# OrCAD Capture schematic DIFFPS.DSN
size A
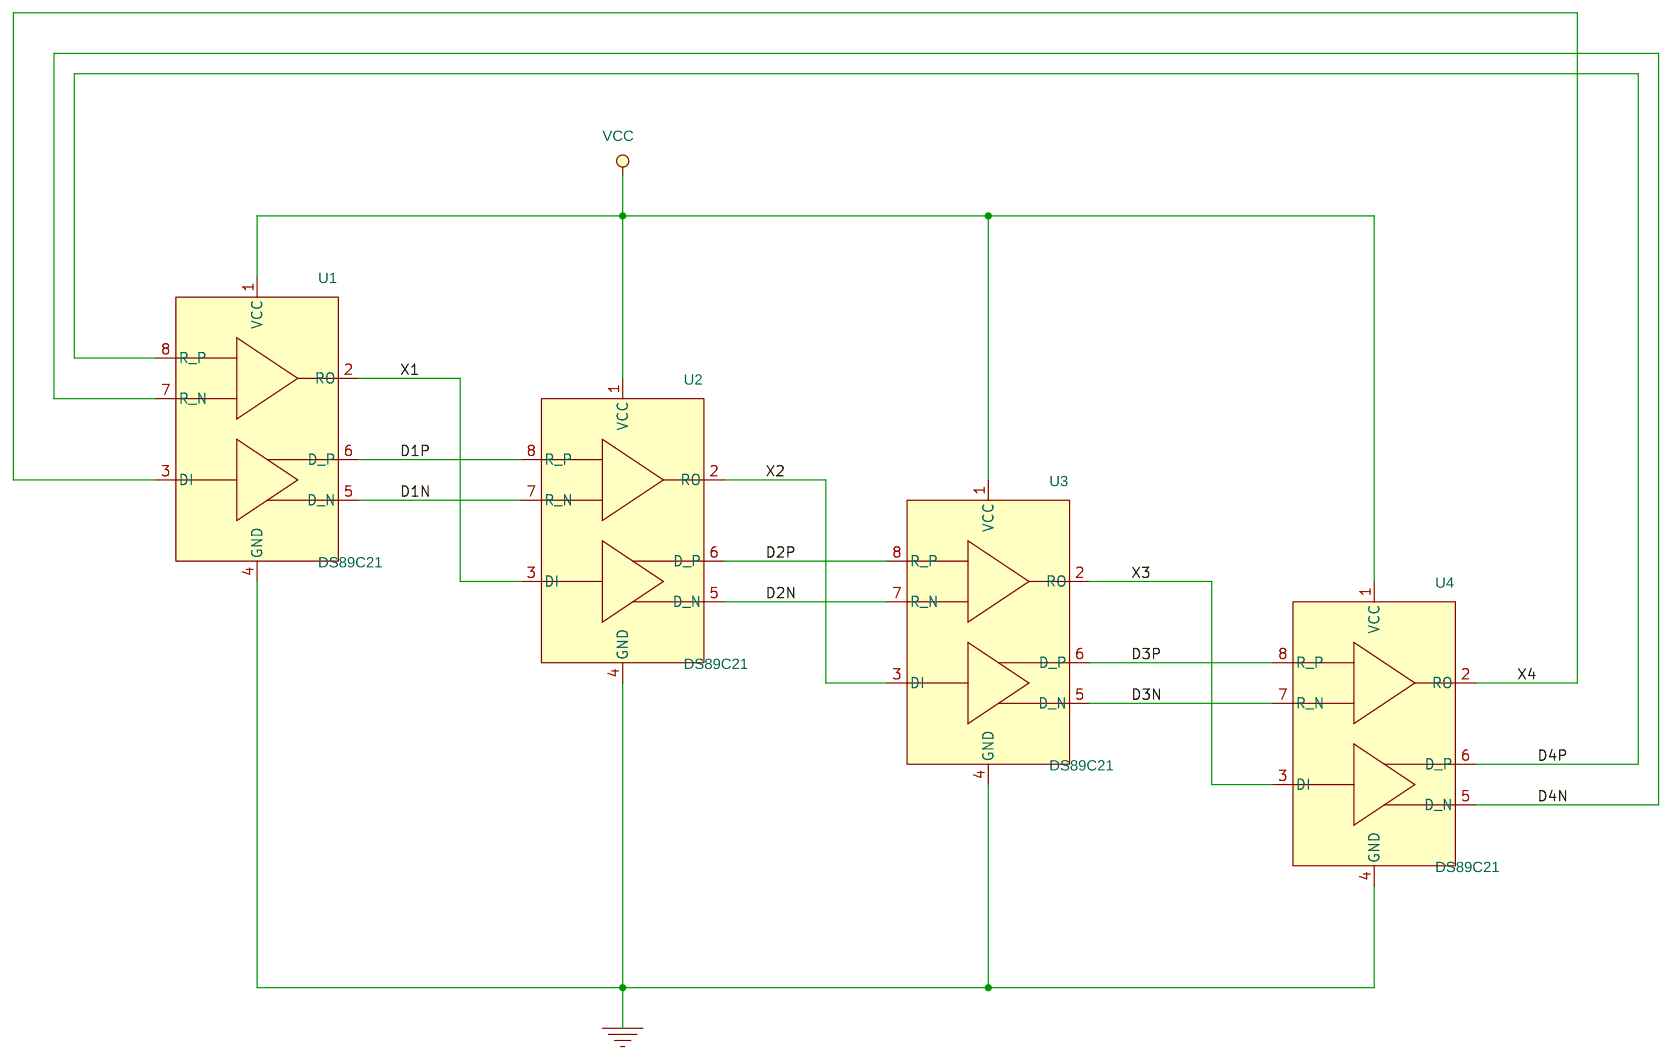
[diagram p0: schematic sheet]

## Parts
U1  DS89C21  [soic127p600x175-8l87n]
U2  DS89C21  [soic127p600x175-8l87n]
U3  DS89C21  [soic127p600x175-8l87n]
U4  DS89C21  [soic127p600x175-8l87n]

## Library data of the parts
U1-U4 = DS89C21

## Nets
GND: U1.4(GND) U2.4(GND) U3.4(GND) U4.4(GND)
VCC: U1.1(VCC) U2.1(VCC) U3.1(VCC) U4.1(VCC)
D1N: U1.5(D_N) U2.7(R_N)
D1P: U1.6(D_P) U2.8(R_P)
D2N: U2.5(D_N) U3.7(R_N)
D2P: U2.6(D_P) U3.8(R_P)
D3N: U3.5(D_N) U4.7(R_N)
D3P: U3.6(D_P) U4.8(R_P)
D4N: U1.7(R_N) U4.5(D_N)
D4P: U1.8(R_P) U4.6(D_P)
X1: U1.2(RO) U2.3(DI)
X2: U2.2(RO) U3.3(DI)
X3: U3.2(RO) U4.3(DI)
X4: U1.3(DI) U4.2(RO)
